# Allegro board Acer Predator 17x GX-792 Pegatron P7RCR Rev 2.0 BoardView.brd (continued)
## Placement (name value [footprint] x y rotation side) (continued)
C7024  0.22UF/16V  [VX_C0402_SMALL]  125.58 110.22 180 bottom
C7025  0.22UF/16V  [VX_C0402_SMALL]  125.58 109.33 180 bottom
C7026  0.1UF/6.3V  [VX_C0402_SMALL]  134.85 95.23 270 top
C7029  0.22UF/16V  [VX_C0402_SMALL]  127.74 110.47 180 bottom
C7030  0.22UF/16V  [VX_C0402_SMALL]  127.74 111.36 180 bottom
C7031  0.22UF/16V  [VX_C0402_SMALL]  124.82 112.63 180 bottom
C7032  0.22UF/16V  [VX_C0402_SMALL]  124.82 111.74 180 bottom
C7033  0.22UF/16V  [VX_C0402_SMALL]  127.74 113.01 180 bottom
C7034  0.22UF/16V  [VX_C0402_SMALL]  127.74 113.9 180 bottom
C7035  0.22UF/16V  [VX_C0402_SMALL]  125.08 114.28 180 bottom
C7036  0.22UF/16V  [VX_C0402_SMALL]  125.08 115.17 180 bottom
C7037  0.22UF/16V  [VX_C0402_SMALL]  127.74 116.44 180 bottom
C7038  0.22UF/16V  [VX_C0402_SMALL]  127.74 115.55 180 bottom
C7039  0.22UF/16V  [VX_C0402_SMALL]  124.82 116.95 180 bottom
C7040  0.22UF/16V  [VX_C0402_SMALL]  124.82 117.84 180 bottom
C7041  0.22UF/16V  [VX_C0402_SMALL]  127.74 118.22 180 bottom
C7042  0.22UF/16V  [VX_C0402_SMALL]  127.74 119.11 180 bottom
C7043  0.22UF/16V  [VX_C0402_SMALL]  124.82 119.49 180 bottom
C7044  0.22UF/16V  [VX_C0402_SMALL]  124.82 120.38 180 bottom
C7049  0.22UF/16V  [VX_C0402_SMALL]  127.74 120.89 180 bottom
C7050  0.22UF/16V  [VX_C0402_SMALL]  127.74 121.77 180 bottom
C7051  0.22UF/16V  [VX_C0402_SMALL]  125.46 122.16 180 bottom
C7052  0.22UF/16V  [VX_C0402_SMALL]  125.46 123.04 180 bottom
C7053  4.7uF/16V  [VX_C0603_SMALL]  135.87 91.17 180 top
C7054  22UF/6.3V  [VX_C0805_H55_SMALL]  123.42 125.46 270 bottom
C7055  22UF/6.3V  [VX_C0805_H55_SMALL]  132.44 82.4 180 top
C7100  0.1UF/6.3V  [VX_C0402_SMALL]  171.02 102 180 top
C7101  0.1UF/6.3V  [VX_C0402_SMALL]  149.21 57.51 180 top
C7102  22UF/6.3V  [VX_C0805_H55_SMALL]  149.21 58.91 180 top
C7103  0.1UF/6.3V  [VX_C0402_SMALL]  162.87 103.28 270 top
C7104  0.1UF/6.3V  [VX_C0402_SMALL]  171.04 95.05 180 top
C7105  0.1UF/6.3V  [VX_C0402_SMALL]  171.18 87.14 180 top
C7106  0.1UF/6.3V  [VX_C0402_SMALL]  167.75 84.52 90 top
C7107  0.1UF/6.3V  [VX_C0402_SMALL]  157.21 103.79 0 top
C7201  0.1UF/6.3V  [VX_C0402_SMALL]  152.15 92.75 0 top
C7202  0.1UF/6.3V  [VX_C0402_SMALL]  149.99 89.72 180 top
C7203  4.7uF/16V  [VX_C0603_SMALL]  134.85 88.52 180 top
C7204  1UF/6.3V  [VX_C0402_SMALL]  143.29 92.21 180 top
C7205  0.1UF/6.3V  [VX_C0402_SMALL]  152.13 90.28 0 top
C7206  10uF/25V  [VX_C0805_H57_SMALL_T02]  136.28 76.77 270 top
C7209  47uF/4V  [VX_C0805_H57_SMALL]  138.16 76.77 270 top
C7210  0.1UF/6.3V  [VX_C0402_SMALL]  150.43 81.66 270 top
C7211  22uF/4V  [VX_C0805_H55_SMALL]  138.8 81.03 270 top
C7212  0.1UF/6.3V  [VX_C0402_SMALL]  162.41 84.06 0 top
C7213  0.1UF/6.3V  [VX_C0402_SMALL]  168.69 103.36 270 top
C7214  0.1UF/6.3V  [VX_C0402_SMALL]  152.13 91.93 0 top
C7215  8.2PF/50V  [VX_C0402_SMALL]  139.55 73.15 270 bottom
C7216  10PF/50V  [VX_C0402_SMALL]  139.55 74.8 90 bottom
C7217  0.1UF/6.3V  [VX_C0402_SMALL]  149.6 83.05 270 top
C7219  4.7uF/16V  [VX_C0603_SMALL]  134.85 87.25 180 top
C7220  0.1UF/6.3V  [VX_C0402_SMALL]  152.13 86.8 0 top
C7221  0.1UF/6.3V  [VX_C0402_SMALL]  152.13 91.12 0 top
C7222  0.1UF/6.3V  [VX_C0402_SMALL]  149.94 87.64 0 top
C7223  0.1UF/6.3V  [VX_C0402_SMALL]  152.13 85.96 0 top
C7225  22UF/6.3V  [VX_C0805_H55_SMALL]  137.24 85.48 90 top
C7226  4.7uF/16V  [VX_C0603_SMALL]  139.71 86.11 180 top
C7230  0.1UF/6.3V  [VX_C0402_SMALL]  152.13 88.55 0 top
C7231  4.7uF/16V  [VX_C0603_SMALL]  134.85 85.98 180 top
C7234  0.1UF/6.3V  [VX_C0402_SMALL]  149.86 85.53 0 top
C7235  1UF/6.3V  [VX_C0402_SMALL]  152.13 87.64 0 top
C7301  1UF/6.3V  [VX_C0402_SMALL]  152.14 89.45 0 top
C7302  0.1UF/6.3V  [VX_C0402_SMALL]  143.29 91.32 180 top
C7400  0.1UF/6.3V  [VX_C0402_SMALL]  131.93 59.8 0 bottom
C7401  220PF/50V  [VX_C0402_SMALL]  152.41 62.57 0 bottom
C7402  220PF/50V  [VX_C0402_SMALL]  152.83 65.13 180 bottom
C7403  220PF/50V  [VX_C0402_SMALL]  148.01 64.75 270 bottom
C7404  220PF/50V  [VX_C0402_SMALL]  150.22 63.23 270 bottom
C7405  220PF/50V  [VX_C0402_SMALL]  134.98 56.5 180 bottom
C7406  220PF/50V  [VX_C0402_SMALL]  136.46 59.16 270 bottom
C7407  220PF/50V  [VX_C0402_SMALL]  136.46 54.08 270 bottom
C7408  220PF/50V  [VX_C0402_SMALL]  136.46 52.43 90 bottom
C7409  0.1UF/6.3V  [VX_C0402_SMALL]  147.73 53.83 90 bottom
C7410  0.1UF/6.3V  [VX_C0402_SMALL]  144.01 53.7 0 bottom
C7501  47uF/4V  [VX_C0805_H57_SMALL]  150.76 107.62 90 top
C7502  47uF/4V  [VX_C0805_H57_SMALL]  152.15 101.51 270 top
C7503  10uF/6.3V  [VX_C0603_H39_SMALL]  166.05 93.91 270 top
C7504  10uF/6.3V  [VX_C0603_H39_SMALL]  158.44 93.95 270 top
C7505  10uF/6.3V  [VX_C0603_H39_SMALL]  155.44 93.95 270 top
C7506  1UF/6.3V  [VX_C0402_SMALL]  171.12 101.18 180 top
C7507  1UF/6.3V  [VX_C0402_SMALL]  171.04 94.2 180 top
C7508  1UF/6.3V  [VX_C0402_SMALL]  171.13 95.9 180 top
C7509  1UF/6.3V  [VX_C0402_SMALL]  161.7 103.29 270 top
C7510  1UF/6.3V  [VX_C0402_SMALL]  160.04 103.29 270 top
C7511  1UF/6.3V  [VX_C0402_SMALL]  171.02 88.84 180 top
C7512  1UF/6.3V  [VX_C0402_SMALL]  171.18 86.3 180 top
C7513  1UF/6.3V  [VX_C0402_SMALL]  160.86 103.29 270 top
C7514  1UF/6.3V  [VX_C0402_SMALL]  164.08 103.79 0 top
C7515  1UF/6.3V  [VX_C0402_SMALL]  167.8 103.36 270 top
C7516  1UF/6.3V  [VX_C0402_SMALL]  164.45 84.51 90 top
C7517  1UF/6.3V  [VX_C0402_SMALL]  169.76 84 0 top
C7518  10uF/6.3V  [VX_C0603_H39_SMALL]  179.55 107.29 180 top
C7519  10uF/6.3V  [VX_C0603_H39_SMALL]  179.13 87.33 270 top
C7520  10uF/6.3V  [VX_C0603_H39_SMALL]  158.16 76.47 0 top
C7521  10uF/6.3V  [VX_C0603_H39_SMALL]  171.75 83.85 135 top
C7522  10uF/6.3V  [VX_C0603_H39_SMALL]  173.77 82.09 315 top
C7523  10uF/6.3V  [VX_C0603_H39_SMALL]  169.8 76.47 180 top
C7531  1UF/6.3V  [VX_C0402_SMALL]  169.53 96.7 0 top
C7532  1UF/6.3V  [VX_C0402_SMALL]  167.96 99.5 0 top
C7533  0.1UF/6.3V  [VX_C0402_SMALL]  157.85 84.41 90 top
C7534  1UF/6.3V  [VX_C0402_SMALL]  171.37 97.12 270 top
C7535  1UF/6.3V  [VX_C0402_SMALL]  164.8 99.5 180 top
C7536  1UF/6.3V  [VX_C0402_SMALL]  164.81 100.89 180 top
C7537  1UF/6.3V  [VX_C0402_SMALL]  158.49 100.99 0 top
C7538  1UF/6.3V  [VX_C0402_SMALL]  155.29 88.32 180 top
C7539  1UF/6.3V  [VX_C0402_SMALL]  167.96 98.1 0 top
C7540  1UF/6.3V  [VX_C0402_SMALL]  166.38 99.5 0 top
C7541  1UF/6.3V  [VX_C0402_SMALL]  160.07 100.99 180 top
C7542  1UF/6.3V  [VX_C0402_SMALL]  156.85 99.52 0 top
C7543  1UF/6.3V  [VX_C0402_SMALL]  163.21 99.5 180 top
C7544  1UF/6.3V  [VX_C0402_SMALL]  153.71 89.72 180 top
C7545  1UF/6.3V  [VX_C0402_SMALL]  153.71 88.32 180 top
C7546  1UF/6.3V  [VX_C0402_SMALL]  158.51 99.51 0 top
C7547  1UF/6.3V  [VX_C0402_SMALL]  156.86 89.72 0 top
C7548  1UF/6.3V  [VX_C0402_SMALL]  158.44 88.32 0 top
C7549  1UF/6.3V  [VX_C0402_SMALL]  156.86 88.32 0 top
C7550  1UF/6.3V  [VX_C0402_SMALL]  166.38 98.1 0 top
C7551  10uF/6.3V  [VX_C0603_H39_SMALL]  165.41 76.48 180 top
C7552  10uF/6.3V  [VX_C0603_H39_SMALL]  171.44 100 180 top
C7553  1UF/6.3V  [VX_C0402_SMALL]  158.74 84.41 90 top
C7554  1UF/6.3V  [VX_C0402_SMALL]  159.98 83.99 0 top
C7555  1UF/6.3V  [VX_C0402_SMALL]  161.2 84.51 90 top
C7556  1UF/6.3V  [VX_C0402_SMALL]  163.61 84.5 90 top
C7557  1UF/6.3V  [VX_C0402_SMALL]  165.65 84.05 0 top
C7558  1UF/6.3V  [VX_C0402_SMALL]  166.85 84.51 90 top
C7559  1UF/6.3V  [VX_C0402_SMALL]  168.56 84.5 90 top
C7560  10uF/6.3V  [VX_C0603_H39_SMALL]  179.55 103.17 180 top
C7561  10uF/6.3V  [VX_C0603_H39_SMALL]  179.55 101.43 180 top
C7562  10uF/6.3V  [VX_C0603_H39_SMALL]  171.77 103.94 225 top
C7563  10uF/6.3V  [VX_C0603_H39_SMALL]  171.4 91.99 180 top
C7564  1UF/6.3V  [VX_C0402_SMALL]  171.16 98.45 180 top
C7565  1UF/6.3V  [VX_C0402_SMALL]  171.02 87.99 180 top
C7566  1UF/6.3V  [VX_C0402_SMALL]  166.95 103.36 270 top
C7567  1UF/6.3V  [VX_C0402_SMALL]  165.67 103.79 180 top
C7568  1UF/6.3V  [VX_C0402_SMALL]  158.81 103.8 180 top
C7569  22uF/6.3V  [VX_C0603_H39_SMALL_T02]  182.56 80.32 270 top
C7570  22uF/6.3V  [VX_C0603_H39_SMALL_T02]  182.56 77.52 90 top
C7571  22uF/6.3V  [VX_C0603_H39_SMALL_T02]  149.81 115.82 270 top
C7572  22uF/6.3V  [VX_C0603_H39_SMALL_T02]  148.5 115.82 270 top
C7573  22uF/6.3V  [VX_C0603_H39_SMALL_T02]  179.01 91.75 90 top
C7574  22uF/6.3V  [VX_C0603_H39_SMALL_T02]  157.1 113.76 180 top
C7575  22uF/6.3V  [VX_C0603_H39_SMALL_T02]  160.72 113.72 0 top
C7576  22uF/6.3V  [VX_C0603_H39_SMALL_T02]  174.22 116.19 180 top
C7577  22uF/6.3V  [VX_C0603_H39_SMALL_T02]  165.92 115.81 0 top
C7578  22UF/6.3V  [VX_C0805_H55_SMALL]  145.78 107.09 270 top
C7579  22UF/6.3V  [VX_C0805_H55_SMALL]  147.87 105.46 270 top
C7580  22UF/6.3V  [VX_C0805_H55_SMALL]  150.02 103.37 270 top
C7581  22UF/6.3V  [VX_C0805_H55_SMALL]  143.77 107.1 270 top
C7582  10uF/6.3V  [VX_C0603_H39_SMALL]  158.74 97.43 270 top
C7583  10uF/6.3V  [VX_C0603_H39_SMALL]  164.66 93.95 90 top
C7584  10uF/6.3V  [VX_C0603_H39_SMALL]  167.59 93.94 90 top
C7585  10uF/6.3V  [VX_C0603_H39_SMALL]  156.94 93.95 270 top
C7586  1UF/6.3V  [VX_C0402_SMALL]  155.28 86.9 180 top
C7587  1UF/6.3V  [VX_C0402_SMALL]  165.67 102.95 0 top
C7588  1UF/6.3V  [VX_C0402_SMALL]  161.7 86.8 180 top
C7589  1UF/6.3V  [VX_C0402_SMALL]  166.4 88.27 180 top
C7590  10uF/6.3V  [VX_C0603_H39_SMALL]  163.17 93.95 270 top
C7591  1UF/6.3V  [VX_C0402_SMALL]  162.41 84.87 0 top
C7592  1UF/6.3V  [VX_C0402_SMALL]  165.65 84.9 0 top
C7593  1UF/6.3V  [VX_C0402_SMALL]  154.83 84.87 180 top
C7594  1UF/6.3V  [VX_C0402_SMALL]  169.53 99.5 0 top
C7595  1UF/6.3V  [VX_C0402_SMALL]  169.53 98.1 0 top
C7596  1UF/6.3V  [VX_C0402_SMALL]  158.46 86.9 0 top
C7597  1UF/6.3V  [VX_C0402_SMALL]  168.02 86.8 0 top
C7598  1UF/6.3V  [VX_C0402_SMALL]  153.71 91.09 180 top
C7599  1UF/6.3V  [VX_C0402_SMALL]  164.86 86.8 180 top
C7601  4.7uF/16V  [VX_C0603_SMALL]  142.67 142.25 180 top
C7602  4.7uF/16V  [VX_C0603_SMALL]  166.9 142.39 180 top
C7603  820PF/50V  [VX_C0402_SMALL]  159.37 134.42 180 top
C7604  820PF/50V  [VX_C0402_SMALL]  154.69 134.96 90 bottom
C7605  22uF/6.3V  [VX_C0603_H39_SMALL_T02]  172.57 139.6 90 top
C7606  22uF/6.3V  [VX_C0603_H39_SMALL_T02]  164.55 125.46 0 top
C7607  22uF/6.3V  [VX_C0603_H39_SMALL_T02]  172.88 131.81 90 top
C7608  22uF/6.3V  [VX_C0603_H39_SMALL_T02]  153.85 128.71 270 top
C7609  22uF/6.3V  [VX_C0603_H39_SMALL_T02]  171.17 142.27 0 top
C7610  10uF/6.3V  [VX_C0603_H39_SMALL]  163.94 142.34 0 top
C7611  10uF/6.3V  [VX_C0603_H39_SMALL]  159.44 140.43 270 bottom
C7612  10uF/6.3V  [VX_C0603_H39_SMALL]  161.26 125.21 180 top
C7613  10uF/6.3V  [VX_C0603_H39_SMALL]  171.14 125.33 0 top
C7614  10uF/6.3V  [VX_C0603_H39_SMALL]  159.57 128.89 270 top
C7615  10uF/6.3V  [VX_C0603_H39_SMALL]  159.45 139.43 90 top
C7616  1UF/6.3V  [VX_C0402_SMALL]  164.93 129.52 270 top
C7617  1UF/6.3V  [VX_C0402_SMALL]  172.36 135.66 270 bottom
C7618  1UF/6.3V  [VX_C0402_SMALL]  140.53 138.56 270 bottom
C7619  1UF/6.3V  [VX_C0402_SMALL]  172.37 135.69 270 top
C7620  1UF/6.3V  [VX_C0402_SMALL]  172.36 137.39 90 bottom
C7621  1UF/6.3V  [VX_C0402_SMALL]  159.72 128.88 270 bottom
C7622  1UF/6.3V  [VX_C0402_SMALL]  159.68 126.61 270 top
C7623  1UF/6.3V  [VX_C0402_SMALL]  167.53 132.24 90 top
C7624  1UF/6.3V  [VX_C0402_SMALL]  159.72 130.57 90 bottom
C7625  1UF/6.3V  [VX_C0402_SMALL]  172.4 137.34 90 top
C7626  1UF/6.3V  [VX_C0402_SMALL]  153.47 131.29 90 bottom
C7627  1UF/6.3V  [VX_C0402_SMALL]  165.56 136 90 top
C7628  1UF/6.3V  [VX_C0402_SMALL]  151.31 142.37 180 bottom
C7629  1UF/6.3V  [VX_C0402_SMALL]  167.7 134.73 0 top
C7630  1UF/6.3V  [VX_C0402_SMALL]  164.95 131.53 90 top
C7631  1UF/6.3V  [VX_C0402_SMALL]  166.83 128.91 90 top
C7632  1UF/6.3V  [VX_C0402_SMALL]  165.59 137.98 270 top
C7633  1UF/6.3V  [VX_C0402_SMALL]  168.48 137.65 0 top
C7634  1UF/6.3V  [VX_C0402_SMALL]  168.93 142.31 0 top
C7635  1UF/6.3V  [VX_C0402_SMALL]  168.71 125.36 180 top
C7636  10uF/6.3V  [VX_C0603_H39_SMALL]  140.61 131.84 270 top
C7637  10uF/6.3V  [VX_C0603_H39_SMALL]  140.68 138.14 270 top
C7638  10uF/6.3V  [VX_C0603_H39_SMALL]  161.25 142.37 0 top
C7639  10uF/6.3V  [VX_C0603_H39_SMALL]  153.53 136.78 270 top
C7640  10uF/6.3V  [VX_C0603_H39_SMALL]  140.43 140.68 270 bottom
C7641  1UF/6.3V  [VX_C0402_SMALL]  140.74 140.55 270 top
C7642  1UF/6.3V  [VX_C0402_SMALL]  146.69 136.05 90 top
C7643  1UF/6.3V  [VX_C0402_SMALL]  147.55 136.68 90 top
C7644  1UF/6.3V  [VX_C0402_SMALL]  147.55 138.6 90 top
C7645  1UF/6.3V  [VX_C0402_SMALL]  148.19 128.86 90 top
C7646  1UF/6.3V  [VX_C0402_SMALL]  148.16 131.5 90 top
C7647  1UF/6.3V  [VX_C0402_SMALL]  146.28 139.99 90 top
C7648  1UF/6.3V  [VX_C0402_SMALL]  146.23 129.47 90 top
C7649  1UF/6.3V  [VX_C0402_SMALL]  153.45 140.67 270 top
C7650  1UF/6.3V  [VX_C0402_SMALL]  153.52 138.84 270 top
C7651  1UF/6.3V  [VX_C0402_SMALL]  159.72 136.63 270 bottom
C7652  1UF/6.3V  [VX_C0402_SMALL]  159.72 138.25 270 bottom
C7653  1UF/6.3V  [VX_C0402_SMALL]  153.35 129.68 90 bottom
C7654  22uF/6.3V  [VX_C0603_H39_SMALL_T02]  147.65 142.25 0 top
C7655  1UF/6.3V  [VX_C0402_SMALL]  146.19 132.04 90 top
C7656  1UF/6.3V  [VX_C0402_SMALL]  140.8 129.27 270 top
C7657  1UF/6.3V  [VX_C0402_SMALL]  153.21 136.93 270 bottom
C7658  1UF/6.3V  [VX_C0402_SMALL]  140.55 136.81 90 bottom
C7659  1UF/6.3V  [VX_C0402_SMALL]  153.35 127.99 90 bottom
C7660  22uF/6.3V  [VX_C0603_H39_SMALL_T02]  153.42 139.68 90 bottom
C7661  1UF/6.3V  [VX_C0402_SMALL]  144.72 142.14 0 top
C7662  1UF/6.3V  [VX_C0402_SMALL]  144.43 126.38 0 top
C7663  22uF/6.3V  [VX_C0603_H39_SMALL_T02]  148.19 142.33 0 bottom
C7664  22uF/6.3V  [VX_C0603_H39_SMALL_T02]  152.04 125.93 0 top
C7665  22uF/6.3V  [VX_C0603_H39_SMALL_T02]  172.83 127.39 270 top
C7666  10uF/6.3V  [VX_C0603_H39_SMALL]  149.21 125.88 180 top
C7701  4.7uF/16V  [VX_C0603_SMALL]  177.23 142.26 180 top
C7702  4.7uF/16V  [VX_C0603_SMALL]  210.6 115.15 90 top
C7703  820PF/50V  [VX_C0402_SMALL]  188.4 134.3 270 bottom
C7704  820PF/50V  [VX_C0402_SMALL]  202.9 122.76 90 top
C7705  10uF/6.3V  [VX_C0603_H39_SMALL]  208.55 122.33 180 bottom
C7706  10uF/6.3V  [VX_C0603_H39_SMALL]  210.47 120.51 270 top
C7707  10uF/6.3V  [VX_C0603_H39_SMALL]  195.73 109.16 180 top
C7708  10uF/6.3V  [VX_C0603_H39_SMALL]  175.31 138.44 270 top
C7709  10uF/6.3V  [VX_C0603_H39_SMALL]  177.29 125.33 180 top
C7710  10uF/6.3V  [VX_C0603_H39_SMALL]  188.04 140.11 90 bottom
C7711  10uF/6.3V  [VX_C0603_H39_SMALL]  185.86 142.37 0 top
C7712  10uF/6.3V  [VX_C0603_H39_SMALL]  175.14 127.18 270 top
C7713  1UF/6.3V  [VX_C0402_SMALL]  180.91 132.11 90 top
C7714  1UF/6.3V  [VX_C0402_SMALL]  188.04 136.28 270 bottom
C7715  1UF/6.3V  [VX_C0402_SMALL]  182.25 138.64 90 top
C7716  1UF/6.3V  [VX_C0402_SMALL]  181.06 135.49 90 top
C7717  1UF/6.3V  [VX_C0402_SMALL]  179.69 136.71 270 top
C7718  1UF/6.3V  [VX_C0402_SMALL]  182.23 136.68 90 top
C7719  1UF/6.3V  [VX_C0402_SMALL]  180.88 129.5 90 top
C7720  1UF/6.3V  [VX_C0402_SMALL]  182.86 129.5 270 top
C7721  1UF/6.3V  [VX_C0402_SMALL]  182.84 131.55 90 top
C7722  10uF/6.3V  [VX_C0603_H39_SMALL]  193.38 118.91 270 top
C7723  10uF/6.3V  [VX_C0603_H39_SMALL]  210.42 117.83 270 top
C7724  1UF/6.3V  [VX_C0402_SMALL]  175.49 129.29 270 top
C7725  1UF/6.3V  [VX_C0402_SMALL]  188.25 127.85 90 bottom
C7726  1UF/6.3V  [VX_C0402_SMALL]  175.39 136.07 270 top
C7727  1UF/6.3V  [VX_C0402_SMALL]  175.44 140.61 270 top
C7728  22uF/6.3V  [VX_C0603_H39_SMALL_T02]  187.93 136.91 270 top
C7729  1UF/6.3V  [VX_C0402_SMALL]  185.05 142.22 180 bottom
C7730  1UF/6.3V  [VX_C0402_SMALL]  175.27 136.16 270 bottom
C7731  1UF/6.3V  [VX_C0402_SMALL]  188.22 129.49 270 bottom
C7732  1UF/6.3V  [VX_C0402_SMALL]  188.04 137.9 90 bottom
C7733  1UF/6.3V  [VX_C0402_SMALL]  172.7 129.6 90 top
C7734  22uF/6.3V  [VX_C0603_H39_SMALL_T02]  187.93 139.85 90 top
C7735  1UF/6.3V  [VX_C0402_SMALL]  179.32 142.18 0 top
C7736  1UF/6.3V  [VX_C0402_SMALL]  179.68 125.72 0 top
C7737  22uF/6.3V  [VX_C0603_H39_SMALL_T02]  175.22 140.25 270 bottom
C7738  22uF/6.3V  [VX_C0603_H39_SMALL_T02]  175.19 131.61 270 top
C7739  22uF/6.3V  [VX_C0603_H39_SMALL_T02]  188.55 129.08 270 top
C7740  10uF/6.3V  [VX_C0603_H39_SMALL]  182.62 142.22 0 top
C7741  1UF/6.3V  [VX_C0402_SMALL]  195.54 122.71 180 top
C7742  1UF/6.3V  [VX_C0402_SMALL]  206.53 116.72 0 top
C7743  1UF/6.3V  [VX_C0402_SMALL]  205.57 113.72 270 top
C7744  1UF/6.3V  [VX_C0402_SMALL]  203.97 116.67 0 top
C7745  1UF/6.3V  [VX_C0402_SMALL]  205.31 115.48 0 top
C7746  1UF/6.3V  [VX_C0402_SMALL]  199.48 117.28 0 top
C7747  1UF/6.3V  [VX_C0402_SMALL]  200.67 114.69 180 top
C7748  1UF/6.3V  [VX_C0402_SMALL]  196.83 117.3 0 top
C7749  1UF/6.3V  [VX_C0402_SMALL]  205.57 109.51 0 bottom
C7750  1UF/6.3V  [VX_C0402_SMALL]  193.4 121.04 90 top
C7751  1UF/6.3V  [VX_C0402_SMALL]  196.26 122.71 0 bottom
C7752  1UF/6.3V  [VX_C0402_SMALL]  197.85 109.2 180 top
C7753  1UF/6.3V  [VX_C0402_SMALL]  205.57 109.58 0 top
C7754  22uF/6.3V  [VX_C0603_H39_SMALL_T02]  200.04 109.18 0 top
C7755  1UF/6.3V  [VX_C0402_SMALL]  203.84 109.53 180 top
C7756  1UF/6.3V  [VX_C0402_SMALL]  198.41 122.77 0 bottom
C7757  1UF/6.3V  [VX_C0402_SMALL]  203.84 109.56 180 bottom
C7758  1UF/6.3V  [VX_C0402_SMALL]  197.29 122.71 180 top
C7759  1UF/6.3V  [VX_C0402_SMALL]  196.83 115.25 0 top
C7760  22uF/6.3V  [VX_C0603_H39_SMALL_T02]  210.5 119.61 90 bottom
C7761  1UF/6.3V  [VX_C0402_SMALL]  193.62 113.73 90 top
C7762  1UF/6.3V  [VX_C0402_SMALL]  210.32 113.11 270 top
C7763  22uF/6.3V  [VX_C0603_H39_SMALL_T02]  205.66 122.48 180 top
C7764  22uF/6.3V  [VX_C0603_H39_SMALL_T02]  205.76 122.36 180 bottom
C7765  22uF/6.3V  [VX_C0603_H39_SMALL_T02]  193.63 110.79 270 top
C7766  10uF/6.3V  [VX_C0603_H39_SMALL]  207.84 109.39 0 bottom
C7801  4.7uF/16V  [VX_C0603_SMALL]  209.9 105.06 90 top
C7802  4.7uF/16V  [VX_C0603_SMALL]  210.42 76.28 270 top
C7803  820PF/50V  [VX_C0402_SMALL]  203.09 93.03 0 bottom
C7804  820PF/50V  [VX_C0402_SMALL]  202.31 87.68 0 top
C7805  10uF/6.3V  [VX_C0603_H39_SMALL]  205.19 93.47 0 top
C7806  10uF/6.3V  [VX_C0603_H39_SMALL]  195.45 74.1 0 top
C7807  10uF/6.3V  [VX_C0603_H39_SMALL]  210.25 85.49 270 top
C7808  10uF/6.3V  [VX_C0603_H39_SMALL]  195.55 93.17 0 top
C7809  10uF/6.3V  [VX_C0603_H39_SMALL]  210.08 95.47 90 top
C7810  10uF/6.3V  [VX_C0603_H39_SMALL]  207.16 106.51 180 top
C7811  10uF/6.3V  [VX_C0603_H39_SMALL]  208.31 87.35 180 bottom
C7812  10uF/6.3V  [VX_C0603_H39_SMALL]  204.82 106.48 0 bottom
C7813  1UF/6.3V  [VX_C0402_SMALL]  198.53 98.74 180 top
C7814  1UF/6.3V  [VX_C0402_SMALL]  205.05 100.64 0 top
C7815  1UF/6.3V  [VX_C0402_SMALL]  209.91 95.78 90 bottom
C7816  1UF/6.3V  [VX_C0402_SMALL]  196.45 100.72 180 top
C7817  1UF/6.3V  [VX_C0402_SMALL]  204.28 99.61 0 top
C7818  1UF/6.3V  [VX_C0402_SMALL]  199.07 100.69 180 top
C7819  1UF/6.3V  [VX_C0402_SMALL]  202.75 103 270 top
C7820  1UF/6.3V  [VX_C0402_SMALL]  206.32 99.35 0 top
C7821  1UF/6.3V  [VX_C0402_SMALL]  197.47 93.4 0 bottom
C7822  10uF/6.3V  [VX_C0603_H39_SMALL]  207.62 74.3 0 top
C7823  10uF/6.3V  [VX_C0603_H39_SMALL]  205.5 87.38 180 bottom
C7824  1UF/6.3V  [VX_C0402_SMALL]  195.43 106.48 180 top
C7825  1UF/6.3V  [VX_C0402_SMALL]  196.98 87.89 180 top
C7826  1UF/6.3V  [VX_C0402_SMALL]  199.22 106.51 180 top
C7827  1UF/6.3V  [VX_C0402_SMALL]  196.58 98.74 0 top
C7828  22uF/6.3V  [VX_C0603_H39_SMALL_T02]  194.76 88.02 180 top
C7829  1UF/6.3V  [VX_C0402_SMALL]  204.73 93.66 180 bottom
C7830  1UF/6.3V  [VX_C0402_SMALL]  197.36 106.46 180 top
C7831  1UF/6.3V  [VX_C0402_SMALL]  197.72 93.2 0 top
C7832  1UF/6.3V  [VX_C0402_SMALL]  196.53 87.84 180 bottom
C7833  1UF/6.3V  [VX_C0402_SMALL]  199.12 93.4 0 bottom
C7834  1UF/6.3V  [VX_C0402_SMALL]  209.56 102.65 270 top
C7835  22uF/6.3V  [VX_C0603_H39_SMALL_T02]  193.39 96.45 90 top
C7836  22uF/6.3V  [VX_C0603_H39_SMALL_T02]  207.98 93.5 180 top
C7837  1UF/6.3V  [VX_C0402_SMALL]  193.45 103.33 270 top
C7838  22uF/6.3V  [VX_C0603_H39_SMALL_T02]  207.05 93.63 180 bottom
C7839  22uF/6.3V  [VX_C0603_H39_SMALL_T02]  205.47 87.39 180 top
C7840  10uF/6.3V  [VX_C0603_H39_SMALL]  210.08 98.21 270 top
C7841  1UF/6.3V  [VX_C0402_SMALL]  203.61 74.45 180 bottom
C7842  1UF/6.3V  [VX_C0402_SMALL]  205.67 81.62 180 top
C7843  1UF/6.3V  [VX_C0402_SMALL]  207.68 80.35 0 top
C7844  1UF/6.3V  [VX_C0402_SMALL]  203.63 81.55 0 top
C7845  1UF/6.3V  [VX_C0402_SMALL]  196.58 82.23 0 top
C7846  1UF/6.3V  [VX_C0402_SMALL]  204.93 80.37 0 top
C7847  1UF/6.3V  [VX_C0402_SMALL]  200.41 79.66 180 top
C7848  1UF/6.3V  [VX_C0402_SMALL]  203.62 74.47 180 top
C7849  1UF/6.3V  [VX_C0402_SMALL]  197.49 74.15 180 top
C7850  1UF/6.3V  [VX_C0402_SMALL]  199.16 82.15 0 top
C7851  1UF/6.3V  [VX_C0402_SMALL]  205.37 74.46 0 bottom
C7852  1UF/6.3V  [VX_C0402_SMALL]  193.3 76.72 270 top
C7853  1UF/6.3V  [VX_C0402_SMALL]  207.73 87.31 180 top
C7854  22uF/6.3V  [VX_C0603_H39_SMALL_T02]  199.71 74.05 180 top
C7855  1UF/6.3V  [VX_C0402_SMALL]  209.91 79.76 90 bottom
C7856  1UF/6.3V  [VX_C0402_SMALL]  198.23 87.81 0 bottom
C7857  1UF/6.3V  [VX_C0402_SMALL]  207.87 122.35 180 top
C7858  1UF/6.3V  [VX_C0402_SMALL]  205.34 74.47 0 top
C7859  1UF/6.3V  [VX_C0402_SMALL]  196.58 80.25 0 top
C7860  22uF/6.3V  [VX_C0603_H39_SMALL_T02]  207.71 106.41 180 bottom
C7861  1UF/6.3V  [VX_C0402_SMALL]  210.29 79.43 90 top
C7862  1UF/6.3V  [VX_C0402_SMALL]  193.24 79.32 90 top
C7863  22uF/6.3V  [VX_C0603_H39_SMALL_T02]  207.63 74.37 0 bottom
C7864  22uF/6.3V  [VX_C0603_H39_SMALL_T02]  204.34 106.59 0 top
C7865  22uF/6.3V  [VX_C0603_H39_SMALL_T02]  193.15 84.01 90 top
C7866  10uF/6.3V  [VX_C0603_H39_SMALL]  210.31 82.79 270 top
C7901  4.7uF/16V  [VX_C0603_SMALL]  182.4 44.1 180 top
C7902  4.7uF/16V  [VX_C0603_SMALL]  160.86 45.49 0 top
C7903  820PF/50V  [VX_C0402_SMALL]  173.67 53.25 90 bottom
C7904  820PF/50V  [VX_C0402_SMALL]  168.05 53.05 0 top
C7905  10uF/6.3V  [VX_C0603_H39_SMALL]  154.84 56.11 270 top
C7906  10uF/6.3V  [VX_C0603_H39_SMALL]  154.9 60.21 90 top
C7907  10uF/6.3V  [VX_C0603_H39_SMALL]  168.26 60.93 90 top
C7908  10uF/6.3V  [VX_C0603_H39_SMALL]  166.32 45.5 180 top
C7909  10uF/6.3V  [VX_C0603_H39_SMALL]  178.34 62.58 0 top
C7910  10uF/6.3V  [VX_C0603_H39_SMALL]  174.44 48.07 270 bottom
C7911  10uF/6.3V  [VX_C0603_H39_SMALL]  175.42 62.55 180 top
C7912  10uF/6.3V  [VX_C0603_H39_SMALL]  167.94 47.34 90 bottom
C7913  1UF/6.3V  [VX_C0402_SMALL]  180.19 51.14 270 top
C7914  1UF/6.3V  [VX_C0402_SMALL]  187 51.77 90 top
C7915  1UF/6.3V  [VX_C0402_SMALL]  186.95 58.58 90 top
C7916  1UF/6.3V  [VX_C0402_SMALL]  181.57 55.73 270 top
C7917  1UF/6.3V  [VX_C0402_SMALL]  183.8 52.81 180 top
C7918  1UF/6.3V  [VX_C0402_SMALL]  179.53 56.34 270 top
C7919  1UF/6.3V  [VX_C0402_SMALL]  180.17 49.18 270 top
C7920  1UF/6.3V  [VX_C0402_SMALL]  181.59 58.35 270 top
C7921  1UF/6.3V  [VX_C0402_SMALL]  179.51 58.27 90 top
C7922  10uF/6.3V  [VX_C0603_H39_SMALL]  167.89 50.21 90 bottom
C7923  10uF/6.3V  [VX_C0603_H39_SMALL]  166.2 62.35 0 top
C7924  1UF/6.3V  [VX_C0402_SMALL]  174.2 57.44 270 bottom
C7925  1UF/6.3V  [VX_C0402_SMALL]  174.2 59.7 270 bottom
C7926  1UF/6.3V  [VX_C0402_SMALL]  176.87 45.68 0 bottom
C7927  1UF/6.3V  [VX_C0402_SMALL]  168.08 58.81 90 top
C7928  22uF/6.3V  [VX_C0603_H39_SMALL_T02]  173.88 59.33 90 top
C7929  1UF/6.3V  [VX_C0402_SMALL]  181.33 51.5 90 top
C7930  1UF/6.3V  [VX_C0402_SMALL]  167.94 47.67 90 top
C7931  1UF/6.3V  [VX_C0402_SMALL]  186.98 50.12 90 top
C7932  1UF/6.3V  [VX_C0402_SMALL]  187.13 46.74 270 bottom
C7933  1UF/6.3V  [VX_C0402_SMALL]  162.13 51.87 270 top
C7934  1UF/6.3V  [VX_C0402_SMALL]  186.97 60.41 270 top
C7935  22uF/6.3V  [VX_C0603_H39_SMALL_T02]  156.55 62.51 180 top
C7936  22uF/6.3V  [VX_C0603_H39_SMALL_T02]  168.04 50.18 90 top
C7937  1UF/6.3V  [VX_C0402_SMALL]  182.63 45.35 180 top
C7938  22uF/6.3V  [VX_C0603_H39_SMALL_T02]  187.31 47.87 270 top
C7939  22uF/6.3V  [VX_C0603_H39_SMALL_T02]  187.38 56.3 90 top
C7940  10uF/6.3V  [VX_C0603_H39_SMALL]  174.3 50.98 90 bottom
C7941  1UF/6.3V  [VX_C0402_SMALL]  168.03 57.33 270 bottom
C7942  1UF/6.3V  [VX_C0402_SMALL]  160.75 49.89 270 top
C7943  1UF/6.3V  [VX_C0402_SMALL]  155.33 52.15 90 top
C7944  1UF/6.3V  [VX_C0402_SMALL]  162.69 58.33 90 top
C7945  1UF/6.3V  [VX_C0402_SMALL]  155.28 50.43 270 top
C7946  1UF/6.3V  [VX_C0402_SMALL]  162.11 49.18 270 top
C7947  1UF/6.3V  [VX_C0402_SMALL]  187.26 50.88 270 bottom
C7948  1UF/6.3V  [VX_C0402_SMALL]  187.26 49.21 90 bottom
C7949  1UF/6.3V  [VX_C0402_SMALL]  175.19 138.06 270 bottom
C7950  1UF/6.3V  [VX_C0402_SMALL]  168.03 58.94 90 bottom
C7951  1UF/6.3V  [VX_C0402_SMALL]  155.23 50.45 270 bottom
C7952  1UF/6.3V  [VX_C0402_SMALL]  162.73 56.37 270 top
C7953  1UF/6.3V  [VX_C0402_SMALL]  155.35 52.15 90 bottom
C7954  22uF/6.3V  [VX_C0603_H39_SMALL_T02]  179.37 45.65 180 top
C7955  1UF/6.3V  [VX_C0402_SMALL]  155.15 48.17 270 bottom
C7956  1UF/6.3V  [VX_C0402_SMALL]  160.1 55.02 90 top
C7957  1UF/6.3V  [VX_C0402_SMALL]  160 52.94 180 top
C7958  1UF/6.3V  [VX_C0402_SMALL]  154.95 58.17 270 top
C7959  1UF/6.3V  [VX_C0402_SMALL]  160.74 58.94 270 top
C7960  22uF/6.3V  [VX_C0603_H39_SMALL_T02]  156.38 45.3 180 top
C7961  1UF/6.3V  [VX_C0402_SMALL]  158.93 62.21 0 top
C7962  1UF/6.3V  [VX_C0402_SMALL]  158.79 45.46 180 top
C7963  22uF/6.3V  [VX_C0603_H39_SMALL_T02]  163.3 62.41 180 top
C7964  22uF/6.3V  [VX_C0603_H39_SMALL_T02]  174.22 51 90 top
C7965  22uF/6.3V  [VX_C0603_H39_SMALL_T02]  155.17 48.16 270 top
C7966  10uF/6.3V  [VX_C0603_H39_SMALL]  176.22 45.42 180 top
C8000  330PF/50V  [VX_C0402_SMALL]  57.13 185.32 0 top
C8001  0.22UF/16V  [VX_C0402_SMALL]  50.91 182.05 0 top
C8002  330PF/50V  [VX_C0402_SMALL]  53.04 184.56 180 top
C8003  330PF/50V  [VX_C0402_SMALL]  50.91 181.16 0 top
C8004  330PF/50V  [VX_C0402_SMALL]  50.61 181.49 270 bottom
C8005  10PF/50V  [VX_C0402_SMALL]  48.49 182.78 180 bottom
C8006  330PF/50V  [VX_C0402_SMALL]  48.49 182.05 0 top
C8007  1200PF/50V  [VX_C0402_SMALL]  48.49 185.42 180 top
C8008  220PF/50V  [VX_C0402_SMALL]  48.49 186.34 180 top
C8009  390PF/50V  [VX_C0402_SMALL]  62.69 186.47 180 bottom
C8010  4700PF/50V  [VX_C0402_SMALL]  58.65 191.16 270 bottom
C8011  0.022UF/25V  [VX_C0402_SMALL]  52.43 177.96 90 bottom
C8012  6800PF/25V  [VX_C0402_SMALL]  48.49 181.89 180 bottom
C8013  330PF/50V  [VX_C0402_SMALL]  66.78 183.29 90 bottom
C8014  330PF/50V  [VX_C0402_SMALL]  61.32 191.16 270 bottom
C8015  18PF/50V  [VX_C0402_SMALL]  61.72 187.41 180 bottom
C8016  8200PF/16V  [VX_C0402_SMALL]  62.21 191.16 270 bottom
C8017  0.022UF/25V  [VX_C0402_SMALL]  54.84 177.96 90 bottom
C8018  2200PF/50V  [VX_C0402_SMALL]  56.62 177.75 270 bottom
C8019  0.022UF/25V  [VX_C0402_SMALL]  53.32 177.96 90 bottom
C8020  0.1UF/25V  [VX_C0402_SMALL]  47.48 177.45 270 bottom
C8021  1000PF/50V  [VX_C0402_SMALL]  63.89 185.12 90 bottom
C8022  330PF/50V  [VX_C0402_SMALL]  63.1 182.91 180 bottom
C8023  0.22UF/16V  [VX_C0402_SMALL]  64.69 182.91 180 bottom
C8024  3300PF/50V  [VX_C0402_SMALL]  56.06 181.77 90 top
C8025  0.22UF/16V  [VX_C0402_SMALL]  54.84 183.67 180 top
C8026  0.068UF/16V  [VX_C0402_SMALL]  49.64 177.45 90 bottom
C8027  0.027UF/25V  [VX_C0402_SMALL]  67.04 181.51 270 bottom
C8028  0.1UF/25V  [VX_C0402_SMALL]  66.15 181.51 90 bottom
C8029  0.022UF/25V  [VX_C0402_SMALL]  67.5 180.24 0 bottom
C8030  0.022UF/25V  [VX_C0402_SMALL]  64.75 181 0 bottom
C8031  8200PF/16V  [VX_C0402_SMALL]  62.68 176.2 180 bottom
C8032  33PF/50V  [VX_C0402_SMALL]  61.83 178.34 180 bottom
C8033  470PF/50V  [VX_C0402_SMALL]  58.2 184.38 0 top
C8034  2200PF/50V  [VX_C0402_SMALL]  71.61 181.89 0 bottom
C8035  330PF/50V  [VX_C0402_SMALL]  61.07 179.73 270 bottom
C8036  0.15uF/10V  [VX_C0402_SMALL]  69.3 181.64 0 bottom
C8053  1000PF/50V  [VX_C0402_SMALL]  70.59 151.62 0 bottom
C8054  0.22UF/16V  [VX_C0402_SMALL]  66.91 148.19 0 bottom
C8055  0.22UF/16V  [VX_C0402_SMALL]  79.48 181.97 270 bottom
C8059  1000PF/50V  [VX_C0402_SMALL]  82.91 178.29 270 bottom
C8060  0.22UF/16V  [VX_C0402_SMALL]  67.16 166.73 0 bottom
C8064  1000PF/50V  [VX_C0402_SMALL]  70.85 170.16 0 bottom
C8065  1UF/16V  [VX_C0402_SMALL]  66.91 147.17 0 bottom
C8066  1UF/16V  [VX_C0402_SMALL]  78.16 182.46 180 bottom
C8067  1UF/16V  [VX_C0402_SMALL]  67.16 165.72 0 bottom
C8068  1UF/25V  [VX_C0402_H24_SMALL]  70.47 144.25 180 bottom
C8069  1UF/25V  [VX_C0402_H24_SMALL]  75.55 178.42 90 bottom
C8070  1UF/25V  [VX_C0402_H24_SMALL]  70.72 162.8 180 bottom
C8071  1500PF/50V  [VX_C0603_SMALL]  74.5 154.82 0 bottom
C8072  1500PF/50V  [VX_C0603_SMALL]  86.59 174.1 180 bottom
C8073  1500PF/50V  [VX_C0603_SMALL]  74.78 170.29 0 bottom
C8074  22UF/6.3V  [VX_C0603_H39_SMALL]  84.44 145.27 0 bottom
C8075  22UF/6.3V  [VX_C0603_H39_SMALL]  84.44 144 0 bottom
C8076  22UF/6.3V  [VX_C0603_H39_SMALL]  90.66 144 180 bottom
C8077  22UF/6.3V  [VX_C0603_H39_SMALL]  90.66 145.27 180 bottom
C8078  22UF/6.3V  [VX_C0603_H39_SMALL]  105.55 117.13 180 top
C8079  22UF/6.3V  [VX_C0603_H39_SMALL]  97.88 120.89 0 top
C8080  22UF/6.3V  [VX_C0603_H39_SMALL]  100.5 120.94 180 top
C8081  22UF/6.3V  [VX_C0603_H39_SMALL]  105.55 119.67 180 top
C8082  22UF/6.3V  [VX_C0603_H39_SMALL]  100.5 119.67 180 top
C8083  22UF/6.3V  [VX_C0603_H39_SMALL]  102.76 120.94 0 top
C8084  22UF/6.3V  [VX_C0603_H39_SMALL]  105.55 120.94 180 top
C8085  22UF/6.3V  [VX_C0603_H39_SMALL]  102.76 119.67 0 top
C8086  0.22UF/16V  [VX_C0402_SMALL]  99.04 156.95 90 top
C8087  10UF/25V  [VX_C0805_H57_SMALL]  90.91 164.25 180 top
C8088  10UF/25V  [VX_C0805_H57_SMALL]  90.91 162.52 180 top
C8089  10UF/25V  [VX_C0805_H57_SMALL]  90.91 160.8 180 top
C8090  1000PF/50V  [VX_C0402_SMALL]  90.33 165.57 180 top
C8091  22UF/6.3V  [VX_C0603_H39_SMALL]  84.44 144 0 top
C8092  22UF/6.3V  [VX_C0603_H39_SMALL]  90.66 145.9 180 top
C8093  22UF/6.3V  [VX_C0603_H39_SMALL]  99.07 139.05 180 top
C8094  22UF/6.3V  [VX_C0603_H39_SMALL]  104.93 137.45 270 top
C8095  22UF/6.3V  [VX_C0603_H39_SMALL]  96.91 141.54 180 top
C8096  22UF/6.3V  [VX_C0603_H39_SMALL]  97.88 119.62 0 top
C8097  22UF/6.3V  [VX_C0603_H39_SMALL]  97.88 118.35 0 top
C8098  22UF/6.3V  [VX_C0603_H39_SMALL]  97.87 140.29 180 top
C8099  22UF/6.3V  [VX_C0603_H39_SMALL]  100.5 117.13 180 top
C8100  0.1UF/10V  [VX_C0402_SMALL]  263.95 60.06 90 top
C8101  1UF/25V  [VX_C0603_SMALL]  265.18 58.12 0 top
C8102  10UF/25V  [VX_C0805_H57_SMALL]  275.7 20.68 270 bottom
C8103  0.1UF/25V  [VX_C0402_SMALL]  273.89 20.43 270 bottom
C8104  10UF/25V  [VX_C0805_H57_SMALL]  267.06 64.37 180 bottom
C8105  10UF/25V  [VX_C0805_H57_SMALL]  267.06 62.59 180 bottom
C8106  0.1UF/25V  [VX_C0402_SMALL]  266.9 65.64 180 bottom
C8107  0.1UF/25V  [VX_C0603_SMALL]  260.08 63.74 270 top
C8108  0.1UF/25V  [VX_C0603_SMALL]  260.58 55.61 270 top
C8109  0.1UF/10V  [VX_C0402_SMALL]  285.98 79.48 90 bottom
C8110  0.1UF/10V  [VX_C0402_SMALL]  256.77 27.79 0 top
C8111  1500PF/50V  [VX_C0402_SMALL]  265.66 67.32 270 bottom
C8112  1500PF/50V  [VX_C0402_SMALL]  273.01 20.43 270 bottom
C8113  39PF/50V  [VX_C0402_SMALL]  258.04 60.69 270 top
C8114  39PF/50V  [VX_C0402_SMALL]  257.89 56.34 180 top
C8115  0.1UF/10V  [VX_C0402_SMALL]  256.77 61.96 180 top
C8116  0.1UF/10V  [VX_C0402_SMALL]  257.89 54.67 180 top
C8117  0.1UF/10V  [VX_C0402_SMALL]  257.66 59.42 180 top
C8118  0.1UF/25V  [VX_C0402_SMALL]  263.25 65.64 180 top
C8119  0.1UF/25V  [VX_C0603_SMALL]  261.98 74.74 270 top
C8120  0.1UF/25V  [VX_C0603_SMALL]  258.81 70.09 180 top
C8121  0.1UF/25V  [VX_C0603_SMALL]  257.41 74.02 270 top
C8122  0.1UF/25V  [VX_C0603_SMALL]  256.52 70.09 180 top
C8123  0.1UF/25V  [VX_C0603_SMALL]  255 75.93 0 top
C8132  10UF/25V  [VX_C0805_H57_SMALL]  276.59 18.35 180 bottom
C8202  1500PF/50V  [VX_C0402_SMALL]  228.2 13.7 0 top
C8203  10UF/25V  [VX_C0805_H57_SMALL]  227.9 11.51 0 top
C8205  0.1UF/25V  [VX_C0603_SMALL]  193.27 16.87 0 top
C8206  1UF/16V  [VX_C0402_SMALL]  225.79 17.51 0 top
C8207  0.22UF/25V  [VX_C0603_SMALL]  218.55 13.95 270 top
C8208  1500PF/50V  [VX_C0402_SMALL]  222.36 17.38 0 top
C8209  22UF/6.3V  [VX_C0603_H39_SMALL]  204.7 11.67 270 top
C8210  22UF/6.3V  [VX_C0603_H39_SMALL]  207.24 11.67 270 top
C8211  22UF/6.3V  [VX_C0603_H39_SMALL]  205.97 11.67 270 top
C8212  22UF/6.3V  [VX_C0603_H39_SMALL]  202.16 11.67 270 top
C8213  22UF/6.3V  [VX_C0603_H39_SMALL]  203.43 11.67 270 top
C8214  10PF/50V  [VX_C0402_SMALL]  228.2 12.81 0 top
C8215  2.2NF/50V  [VX_C0402_SMALL]  227.18 14.97 90 top
C8216  220PF/50V  [VX_C0402_SMALL]  212.32 10.9 0 top
C8300  10UF/6.3V  [VX_C0603_SMALL]  24.29 51.92 270 top
C8301  10UF/6.3V  [VX_C0603_SMALL]  23.02 51.92 270 top
C8302  0.1UF/10V  [VX_C0402_SMALL]  25.43 53.32 90 top
C8303  0.033UF/16V  [VX_C0402_SMALL]  24.74 47.92 270 top
C8304  1500PF/50V  [VX_C0402_SMALL]  19.54 67.93 270 top
C8305  0.1UF/25V  [VX_C0402_SMALL]  20.43 67.93 270 top
C8306  10UF/25V  [VX_C0805_H57_SMALL]  21.7 67.29 270 top
C8307  10UF/25V  [VX_C0805_H57_SMALL]  23.48 67.29 270 top
C8308  10UF/6.3V  [VX_C0603_SMALL]  26.95 53.58 180 top
C8309  0.1UF/25V  [VX_C0603_SMALL]  31.14 53.58 270 top
C8310  0.1UF/25V  [VX_C0402_SMALL]  30.21 46.34 0 top
C8311  22UF/6.3V  [VX_C0603_H39_SMALL]  35.39 100.34 180 top
C8312  22UF/6.3V  [VX_C0603_H39_SMALL]  35.39 101.61 180 top
C8313  22UF/6.3V  [VX_C0603_H39_SMALL]  35.39 102.88 180 top
C8314  1500PF/50V  [VX_C0402_SMALL]  27.54 68.05 0 top
C8315  22UF/6.3V  [VX_C0603_H39_SMALL]  35.39 99.07 180 top
C8316  22UF/6.3V  [VX_C0603_H39_SMALL]  35.39 97.8 180 top
C8317  22UF/6.3V  [VX_C0603_H39_SMALL]  35.39 96.53 180 top
C8318  0.1UF/10V  [VX_C0402_SMALL]  32.29 49.13 90 top
C8319  0.01UF/16V  [VX_C0402_SMALL]  27.33 45.96 270 top
C8320  0.01UF/50V  [VX_C0402_SMALL]  24.44 45.96 90 top
C8321  0.01UF/50V  [VX_C0402_SMALL]  24.87 44.69 0 top
C8322  1500PF/50V  [VX_C0402_SMALL]  28.22 45.96 270 top
C8323  10PF/50V  [VX_C0402_SMALL]  19.36 75.11 180 top
C8324  2.2NF/50V  [VX_C0402_SMALL]  19.36 75.94 180 top
C8325  10PF/50V  [VX_C0402_SMALL]  42.78 114.54 90 top
C8326  2.2NF/50V  [VX_C0402_SMALL]  41.89 114.54 90 top
C8327  10PF/50V  [VX_C0402_SMALL]  21.97 51.98 270 top
C8328  2.2NF/50V  [VX_C0402_SMALL]  21.09 51.98 270 top
C8400  1000PF/50V  [VX_C0402_SMALL]  219.87 25.71 90 top
C8401  10UF/6.3V  [VX_C0603_SMALL]  215.25 28.3 180 top
C8402  0.1UF/10V  [VX_C0402_SMALL]  221.6 30.08 0 top
C8404  10UF/6.3V  [VX_C0603_SMALL]  224.52 29.57 90 top
C8601  1500PF/50V  [VX_C0402_SMALL]  123.65 56.62 0 top
C8602  0.1UF/10V  [VX_C0402_SMALL]  118.73 61.07 180 top
C8603  22UF/6.3V  [VX_C0805_H57_SMALL]  127.82 74.4 0 top
C8604  0.22UF/25V  [VX_C0603_SMALL]  116.61 64.86 270 top
C8605  220PF/50V  [VX_C0402_SMALL]  123.55 58.02 90 bottom
C8606  22UF/6.3V  [VX_C0805_H57_SMALL]  127.82 72.63 0 top
C8607  0.1UF/16V  [VX_C0402_SMALL]  121.82 57.16 90 bottom
C8608  22UF/6.3V  [VX_C0805_H57_SMALL]  122.04 72.87 180 top
C8609  22UF/6.3V  [VX_C0805_H57_SMALL]  122.03 74.66 180 top
C8610  1500PF/50V  [VX_C0603_SMALL]  126.17 59.93 270 bottom
C8611  0.1UF/10V  [VX_C0402_SMALL]  125.84 61.2 0 top
C8612  10UF/25V  [VX_C0805_H57_SMALL]  123.45 53.51 0 top
C8613  10UF/25V  [VX_C0805_H57_SMALL]  123.45 55.29 0 top
C8614  10PF/50V  [VX_C0402_SMALL]  123.95 85.07 180 top
C8615  2.2NF/50V  [VX_C0402_SMALL]  123.95 84.23 180 top
C8616  22UF/6.3V  [VX_C0805_H57_SMALL]  122.03 76.44 180 top
C8701  4700PF/50V  [VX_C0402_SMALL]  131.93 164.7 90 top
C8702  1500PF/50V  [VX_C0402_SMALL]  129.27 162.34 90 bottom
C8703  0.01UF/25V  [VX_C0402_SMALL]  130.16 164.7 90 top
C8704  0.01UF/25V  [VX_C0402_SMALL]  128.38 164.7 90 top
C8705  0.068UF/10V  [VX_C0402_SMALL]  121.39 153.14 90 top
C8706  0.068UF/10V  [VX_C0402_SMALL]  117.84 153.98 0 top
C8707  0.068UF/10V  [VX_C0402_SMALL]  117.84 156.67 0 top
C8708  0.068UF/10V  [VX_C0402_SMALL]  117.84 159.21 0 top
C8709  0.068UF/10V  [VX_C0402_SMALL]  117.84 160.97 0 top
C8710  0.068UF/10V  [VX_C0402_SMALL]  117.58 162.59 270 top
C8711  0.068UF/10V  [VX_C0402_SMALL]  118.5 162.59 270 top
C8712  0.068UF/10V  [VX_C0402_SMALL]  119.39 162.59 270 top
C8713  0.33UF/10V  [VX_C0402_SMALL]  122.28 153.14 270 top
C8714  1000PF/50V  [VX_C0402_SMALL]  123.68 152.51 180 top
C8715  820PF/50V  [VX_C0402_SMALL]  123.68 154.03 180 top
C8716  1000PF/50V  [VX_C0402_SMALL]  125.84 153.14 270 bottom
C8717  2200PF/50V  [VX_C0402_SMALL]  130.32 153.83 270 top
C8718  47PF/50V  [VX_C0402_SMALL]  129.43 153.83 270 top
C8719  330PF/50V  [VX_C0402_SMALL]  128.67 152 270 top
C8720  1000PF/50V  [VX_C0402_SMALL]  131.22 156.06 90 top
C8721  1UF/10V  [VX_C0603_SMALL]  129.77 155.81 0 bottom
C8722  2.2UF/6.3V  [VX_C0603_SMALL]  186.04 164.19 270 top
C8723  0.22UF/25V  [VX_C0603_SMALL]  180.7 163.05 90 top
C8724  10UF/25V  [VX_C0805_H57_SMALL]  166.86 188.58 90 top
C8725  10UF/25V  [VX_C0805_H57_SMALL]  130.54 181.95 90 top
C8726  1500PF/50V  [VX_C0603_SMALL]  184.77 180.45 180 bottom
C8727  2.2UF/6.3V  [VX_C0603_SMALL]  146.54 164.95 270 top
C8728  0.22UF/25V  [VX_C0603_SMALL]  141.33 163.81 90 top
C8729  10UF/25V  [VX_C0805_H57_SMALL]  134.08 181.95 90 top
C8730  10UF/25V  [VX_C0805_H57_SMALL]  135.86 181.95 90 top
C8731  1500PF/50V  [VX_C0603_SMALL]  147.43 178.16 90 bottom
C8732  2.2UF/6.3V  [VX_C0603_SMALL]  160.94 164.95 270 top
C8733  0.22UF/25V  [VX_C0603_SMALL]  155.68 163.81 90 top
C8734  10UF/25V  [VX_C0805_H57_SMALL]  146.16 189.47 90 top
C8735  10UF/25V  [VX_C0805_H57_SMALL]  156.83 189.72 90 top
C8736  1500PF/50V  [VX_C0603_SMALL]  148.7 178.16 90 bottom
C8737  2.2UF/6.3V  [VX_C0603_SMALL]  173.97 164.95 270 top
C8738  0.22UF/25V  [VX_C0603_SMALL]  168.64 163.81 90 top
C8739  10UF/25V  [VX_C0805_H57_SMALL]  180.32 188.58 90 top
C8740  10UF/25V  [VX_C0805_H57_SMALL]  168.64 188.58 90 top
C8741  1500PF/50V  [VX_C0603_SMALL]  161.78 178.16 90 bottom
C8752  22UF/6.3V  [VX_C0805_H57_SMALL]  135.54 114.99 0 top
C8753  22UF/6.3V  [VX_C0805_H57_SMALL]  141.38 120.64 270 top
C8754  22UF/6.3V  [VX_C0805_H57_SMALL]  135.42 145.88 180 bottom
C8755  22UF/6.3V  [VX_C0805_H57_SMALL]  180.27 146.88 180 bottom
C8756  22UF/6.3V  [VX_C0805_H57_SMALL]  142.6 145.45 0 top
C8757  22UF/6.3V  [VX_C0805_H57_SMALL]  180.17 146.95 180 top
C8758  22UF/6.3V  [VX_C0805_H57_SMALL]  180.27 148.71 180 bottom
C8759  22UF/6.3V  [VX_C0805_H57_SMALL]  135.42 147.79 180 bottom
C8760  22UF/6.3V  [VX_C0805_H57_SMALL]  180.27 145.06 180 bottom
C8761  22UF/6.3V  [VX_C0805_H57_SMALL]  135.13 145.42 180 top
C8762  22UF/6.3V  [VX_C0805_H57_SMALL]  137.91 143.84 270 bottom
C8763  22UF/6.3V  [VX_C0805_H57_SMALL]  143.62 144.63 0 bottom
C8764  22UF/6.3V  [VX_C0805_H57_SMALL]  181.21 154.77 90 top
C8765  22UF/6.3V  [VX_C0805_H57_SMALL]  170.03 144.76 0 bottom
C8766  22UF/6.3V  [VX_C0805_H57_SMALL]  180.17 152.41 180 top
C8767  22UF/6.3V  [VX_C0805_H57_SMALL]  156.7 144.76 180 bottom
C8768  0.1UF/25V  [VX_C0603_SMALL]  126.09 157.72 180 bottom
C8769  10UF/25V  [VX_C0805_H57_SMALL]  174.61 188.58 90 top
C8770  10UF/25V  [VX_C0805_H57_SMALL]  178.54 188.58 90 top
C8771  10UF/25V  [VX_C0805_H57_SMALL]  155.05 189.72 90 top
C8772  10UF/25V  [VX_C0805_H57_SMALL]  144.38 189.47 90 top
C8773  10UF/25V  [VX_C0805_H57_SMALL]  161.27 188.58 90 top
C8774  10UF/25V  [VX_C0805_H57_SMALL]  163.05 188.58 90 top
C8775  10UF/25V  [VX_C0805_H57_SMALL]  132.31 181.95 90 top
C8776  10UF/25V  [VX_C0805_H57_SMALL]  172.83 188.58 90 top
C8781  22UF/6.3V  [VX_C0805_H57_SMALL]  139.63 120.65 270 top
C8782  22UF/6.3V  [VX_C0805_H57_SMALL]  137.89 120.66 270 top
C8783  22UF/6.3V  [VX_C0805_H57_SMALL]  180.17 150.5 180 top
C8784  22UF/6.3V  [VX_C0805_H57_SMALL]  180.27 150.53 180 bottom
C8785  22UF/6.3V  [VX_C0805_H57_SMALL]  180.17 148.72 180 top
C8786  22UF/6.3V  [VX_C0805_H57_SMALL]  135.54 120.39 0 top
C8787  22UF/6.3V  [VX_C0805_H57_SMALL]  135.54 118.59 0 top
C8788  22UF/6.3V  [VX_C0805_H57_SMALL]  135.54 116.79 0 top
C8800  470PF/50V  [VX_C0402_SMALL]  9.15 82.43 0 top
C8801  0.01UF/50V  [VX_C0402_SMALL]  10.83 80.86 270 top
C8802  1500PF/50V  [VX_C0402_SMALL]  299.57 14.61 180 top
C8803  10UF/25V  [VX_C0805_H57_SMALL]  289.01 15.02 270 top
C8804  1500PF/50V  [VX_C0402_SMALL]  290.38 15.27 90 top
C8806  2.2UF/25V  [VX_C1206_H49]  10.9 71.74 90 top
C8807  0.1UF/25V  [VX_C0402_SMALL]  279.3 38.34 0 top
C8808  0.1UF/25V  [VX_C0402_SMALL]  278.54 37.07 90 top
C8809  0.1UF/25V  [VX_C0402_SMALL]  279.94 37.07 90 top
C8810  1500PF/50V  [VX_C0402_SMALL]  281.16 18.65 180 top
C8811  10UF/25V  [VX_C0805_H57_SMALL]  281.16 16.36 180 top
C8812  10UF/25V  [VX_C0805_H57_SMALL]  281.16 14.59 180 top
C8813  0.1UF/25V  [VX_C0402_SMALL]  281.16 17.76 180 top
C8814  0.1UF/10V  [VX_C0402_SMALL]  269.5 35.29 90 top
C8815  100PF/50V  [VX_C0402_SMALL]  146.03 16.49 270 bottom
C8816  0.47UF/25V  [VX_C0603_SMALL]  281.16 35.08 180 top
C8817  0.047UF/16V  [VX_C0402_SMALL]  281.29 33.13 0 top
C8818  10UF/25V  [VX_C0805_H57_SMALL]  301.35 15.48 270 top
C8819  10UF/25V  [VX_C0805_H57_SMALL]  303.13 15.48 270 top
C8820  10UF/25V  [VX_C0805_H57_SMALL]  304.91 15.48 270 top
C8821  1UF/25V  [VX_C0603_SMALL]  280.78 30.08 270 top
C8822  0.1UF/25V  [VX_C0402_SMALL]  281.16 19.67 180 top
C8823  0.1UF/25V  [VX_C0402_SMALL]  286.49 28 270 top
C8824  0.01UF/50V  [VX_C0402_SMALL]  277.86 28.86 90 top
C8825  0.1UF/25V  [VX_C0402_SMALL]  284.59 28.64 180 top
C8826  0.1UF/25V  [VX_C0402_SMALL]  284.59 27.24 180 top
C8827  0.022UF/16V  [VX_C0402_SMALL]  270.87 38.21 180 top
C8839  100PF/50V  [VX_C0402_SMALL]  145.14 15.98 270 bottom
C8900  0.1UF/25V  [VX_C0402_SMALL]  230.51 96.3 90 top
C8901  10UF/25V  [VX_C0805_H57_SMALL]  227.44 96.63 90 top
C8902  10UF/25V  [VX_C0805_H57_SMALL]  229.22 96.63 90 top
C8903  0.22UF/16V  [VX_C0402_SMALL]  245.34 81.26 90 top
C8904  0.01UF/16V  [VX_C0402_SMALL]  254.34 81.29 90 bottom
C8906  1500PF/50V  [VX_C0402_SMALL]  219.82 98.28 180 top
C8907  100PF/50V  [VX_C0402_SMALL]  251.24 85.81 180 top
C8908  0.1UF/10V  [VX_C0402_SMALL]  252.46 82.66 0 bottom
C8909  2700PF/50V  [VX_C0402_SMALL]  252.33 82.02 0 top
C8910  2.2UF/6.3V  [VX_C0603_SMALL]  244.46 82.02 0 bottom
C8912  390PF/50V  [VX_C0402_SMALL]  249.94 86.72 90 top
C8915  0.22UF/25V  [VX_C0603_SMALL]  251.87 89.19 0 top
C8916  10PF/50V  [VX_C0402_SMALL]  211.56 97.97 0 top
C8925  10UF/25V  [VX_C0805_H57_SMALL]  236.28 93.28 90 top
C8926  0.1UF/25V  [VX_C0402_SMALL]  237.67 93.28 90 top
C8927  1500PF/50V  [VX_C0402_SMALL]  242.8 91.42 0 bottom
C8928  10UF/25V  [VX_C0805_H57_SMALL]  234.47 93.28 90 top
C8929  0.22UF/16V  [VX_C0402_SMALL]  245.47 85.2 270 top
C09100  1UF/6.3V  [VX_C0201_H14]  86.25 115.17 0 top
C9100  0.01UF/16V  [VX_C0402_SMALL]  197.31 35.52 270 top
C09101  1UF/6.3V  [VX_C0201_H14]  81.3 121.95 0 top
C9101  4.7UF/10V  [VX_C0402_H26_SMALL]  193.86 34.73 0 top
C09102  1UF/6.3V  [VX_C0201_H14]  90.31 122.71 0 top
C9103  0.047UF/16V  [VX_C0402_SMALL]  197.8 38.08 0 top
C09103  1UF/6.3V  [VX_C0201_H14]  86 125.76 180 top
C09104  1UF/6.3V  [VX_C0201_H14]  87.14 123.48 180 top
C09105  1UF/6.3V  [VX_C0201_H14]  85.62 122.71 0 top
C9105  0.1UF/10V  [VX_C0402_SMALL]  197.8 37.17 0 top
C9106  0.01UF/16V  [VX_C0402_SMALL]  132.52 75.11 270 top
C09106  1UF/6.3V  [VX_C0201_H14]  90.31 121.95 0 top
C09107  1UF/6.3V  [VX_C0201_H14]  88.41 125.76 0 top
C9107  4.7UF/10V  [VX_C0402_H26_SMALL]  195.76 39.71 180 top
C9108  1000PF/50V  [VX_C0402_SMALL]  191.9 37.72 180 top
C09108  1UF/6.3V  [VX_C0201_H14]  90.72 125.76 180 top
C09109  1UF/6.3V  [VX_C0201_H14]  90.31 123.48 0 top
C9109  1000PF/50V  [VX_C0402_SMALL]  191.9 36.15 180 top
C09110  1UF/6.3V  [VX_C0201_H14]  91.08 115.14 0 top
C9110  0.1UF/10V  [VX_C0402_SMALL]  194.16 39.71 0 top
C09111  1UF/6.3V  [VX_C0201_H14]  91.08 114.38 0 top
C9111  0.068UF/16V  [VX_C0402_SMALL]  243.69 19.54 0 top
C09112  1UF/6.3V  [VX_C0201_H14]  93.62 114.46 0 top
C9112  0.1UF/10V  [VX_C0402_SMALL]  240.14 16.11 0 top
C09113  1UF/6.3V  [VX_C0201_H14]  91.84 121.95 180 top
C9113  0.1UF/10V  [VX_C0402_SMALL]  239.63 20.94 0 top
C9114  0.1UF/10V  [VX_C0402_SMALL]  243.69 18.65 0 top
C09114  1UF/6.3V  [VX_C0201_H14]  86.25 112.88 0 top
C9115  1UF/10V  [VX_C0402_SMALL]  241.92 20.94 180 top
C09115  1UF/6.3V  [VX_C0201_H14]  83.46 113.57 180 top
C9116  1000PF/50V  [VX_C0402_SMALL]  238.11 19.29 180 top
C09116  1UF/6.3V  [VX_C0201_H14]  81.3 127.67 180 top
C09117  1UF/6.3V  [VX_C0201_H14]  86 127.67 180 top
C9117  1000PF/50V  [VX_C0402_SMALL]  238.11 18.02 180 top
C9118  0.033UF/16V  [VX_C0402_SMALL]  260.33 77.86 270 top
C09118  1UF/6.3V  [VX_C0201_H14]  93.11 127.67 0 top
C9119  0.1UF/10V  [VX_C0402_SMALL]  257.28 81.77 270 top
C09119  1UF/6.3V  [VX_C0201_H14]  81.3 120.43 0 top
C09120  1UF/6.3V  [VX_C0201_H14]  82.82 121.19 180 top
C9120  0.033UF/16V  [VX_C0402_SMALL]  259.01 80.3 180 bottom
C9121  1UF/10V  [VX_C0402_SMALL]  261.98 79.36 90 top
C09121  1UF/6.3V  [VX_C0201_H14]  90.31 121.19 0 top
C09122  1UF/6.3V  [VX_C0201_H14]  81.3 123.48 0 top
C9122  1UF/10V  [VX_C0402_SMALL]  258.3 78.19 270 top
C09123  1UF/6.3V  [VX_C0201_H14]  87.14 121.19 180 top
C9123  1000PF/50V  [VX_C0402_SMALL]  259.95 84.06 90 top
C9124  1000PF/50V  [VX_C0402_SMALL]  259.06 84.06 90 top
C09124  1UF/6.3V  [VX_C0201_H14]  86.25 113.65 0 top
C09125  1UF/6.3V  [VX_C0201_H14]  89.04 113.7 180 top
C9125  0.1UF/10V  [VX_C0402_SMALL]  260.84 84.06 90 top
C09126  1UF/6.3V  [VX_C0201_H14]  89.04 112.97 180 top
C09127  1UF/6.3V  [VX_C0201_H14]  85.62 121.19 0 top
C09128  1UF/6.3V  [VX_C0201_H14]  81.3 122.71 0 top
C09129  1UF/6.3V  [VX_C0201_H14]  90.72 127.67 180 top
C09130  1UF/6.3V  [VX_C0201_H14]  85.62 121.95 0 top
C9133  0.1UF/10V  [VX_C0402_SMALL]  238.36 23.48 180 top
C9134  0.01UF/16V  [VX_C0402_SMALL]  238.36 24.37 180 top
C9135  0.1UF/10V  [VX_C0402_SMALL]  135.87 92.21 180 top
C9136  0.1UF/10V  [VX_C0402_SMALL]  193.86 33.84 0 top
C9200  2.2UF/6.3V  [VX_C0402_SMALL]  176.38 37.45 180 top
C9400  1500PF/50V  [VX_C0402_SMALL]  100.56 168 90 bottom
C9401  10UF/25V  [VX_C0805_H57_SMALL]  97.39 168 90 bottom
C9402  10UF/25V  [VX_C0805_H57_SMALL]  99.17 168 90 bottom
C9403  1UF/16V  [VX_C0402_SMALL]  102.34 171.56 90 bottom
C9405  0.22UF/25V  [VX_C0603_SMALL]  107.3 165.21 180 bottom
C9406  22UF/6.3V  [VX_C0603_H39_SMALL]  117.07 162.03 0 bottom
C9407  22UF/6.3V  [VX_C0603_H39_SMALL]  106.55 159.24 180 bottom
C9408  22UF/6.3V  [VX_C0603_H39_SMALL]  106.55 160.51 180 bottom
C9409  22UF/6.3V  [VX_C0603_H39_SMALL]  117.07 160.51 0 bottom
C9410  22UF/6.3V  [VX_C0603_H39_SMALL]  117.07 163.56 0 bottom
C9411  0.01UF/16V  [VX_C0402_SMALL]  101.2 164.19 180 bottom
C9412  1500PF/50V  [VX_C0402_SMALL]  104.98 171.58 90 bottom
C9414  1UF/6.3V  [VX_C0402_SMALL]  106.79 156.88 180 bottom
C9415  2.2NF/50V  [VX_C0402_SMALL]  106.79 156 180 bottom
C9416  220PF/50V  [VX_C0402_SMALL]  107.42 162.8 180 bottom
C9500  1500PF/50V  [VX_C0402_SMALL]  87.61 5.57 270 top
C9501  10UF/25V  [VX_C0805_H57_SMALL]  86.21 5.57 270 top
C9502  10UF/25V  [VX_C0805_H57_SMALL]  84.44 5.57 270 top
C9503  0.1UF/10V  [VX_C0402_SMALL]  91.27 2.85 180 top
C9504  0.1UF/10V  [VX_C0402_SMALL]  91.04 9.25 90 top
C9505  0.22UF/25V  [VX_C0603_SMALL]  93.33 7.22 90 top
C9506  22UF/6.3V  [VX_C0603_H39_SMALL]  106.15 8.11 270 top
C9507  22UF/6.3V  [VX_C0603_H39_SMALL]  107.8 8.11 270 top
C9508  22UF/6.3V  [VX_C0603_H39_SMALL]  104.25 12.3 90 top
C9509  22UF/6.3V  [VX_C0603_H39_SMALL]  106.03 12.3 90 top
C9510  22UF/6.3V  [VX_C0603_H39_SMALL]  107.8 12.3 90 top
C9511  0.1UF/10V  [VX_C0402_SMALL]  97.8 13.57 90 bottom
C9512  1500PF/50V  [VX_C0402_SMALL]  93.4 2.52 180 top
C9513  220PF/50V  [VX_C0402_SMALL]  92.82 11.41 270 top
C9514  10PF/50V  [VX_C0402_SMALL]  115.93 12.94 0 top
C9515  2.2NF/50V  [VX_C0402_SMALL]  115.93 12.05 0 top
C9600  22UF/6.3V  [VX_C0603_H39_SMALL]  116.95 134.09 180 bottom
C9601  220PF/50V  [VX_C0402_SMALL]  113.52 150.35 0 bottom
C9602  22UF/6.3V  [VX_C0603_H39_SMALL]  116.95 135.49 180 bottom
C9603  0.1UF/25V  [VX_C0402_SMALL]  114.03 143.87 0 bottom
C9604  10UF/25V  [VX_C0805_H57_SMALL]  118.34 152.18 0 bottom
C9605  10UF/25V  [VX_C0805_H57_SMALL]  118.34 153.96 0 bottom
C9606  10PF/50V  [VX_C0402_SMALL]  127.36 125.08 270 bottom
C9607  2.2NF/50V  [VX_C0402_SMALL]  116.95 136.63 180 bottom
C9608  0.1UF/10V  [VX_C0402_SMALL]  121.6 147.25 0 bottom
C9609  0.22UF/25V  [VX_C0603_SMALL]  116.95 145.14 180 bottom
C9610  0.1UF/25V  [VX_C0402_SMALL]  118.09 150.86 0 bottom
C9611  1500PF/50V  [VX_C0402_SMALL]  120.53 148.11 90 top
C9612  0.1UF/10V  [VX_C0402_SMALL]  114.66 147.3 180 bottom
C9613  22UF/6.3V  [VX_C0603_H39_SMALL]  119.74 132.32 180 bottom
C9614  22UF/6.3V  [VX_C0603_H39_SMALL]  119.87 130.79 180 bottom
C9701  0.22UF/25V  [VX_C0603_SMALL]  202.14 184.4 180 top
C9702  10UF/25V  [VX_C0805_H57_SMALL]  191.5 177.65 180 top
C9703  2700PF/50V  [VX_C0402_SMALL]  200.77 189.24 180 bottom
C9704  0.22UF/25V  [VX_C0603_SMALL]  196.58 184.89 0 top
C9705  0.1UF/6.3V  [VX_C0402_SMALL]  189.08 152.53 180 bottom
C9706  0.1UF/6.3V  [VX_C0402_SMALL]  200.79 146.46 0 bottom
C9707  10UF/6.3V  [VX_C0603_SMALL]  93.07 177.15 180 top
C9708  10UF/6.3V  [VX_C0603_SMALL]  89.64 178.92 270 top
C9709  2.2UF/6.3V  [VX_C0603_SMALL]  200.77 185.53 90 bottom
C9710  10UF/25V  [VX_C0805_H57_SMALL]  206.48 177.91 0 top
C9711  390PF/50V  [VX_C0402_SMALL]  196.32 189.34 180 top
C9712  1500PF/50V  [VX_C0603_SMALL]  210.34 173.46 90 bottom
C9713  0.47UF/10V  [VX_C0402_SMALL]  206.28 187.51 0 top
C9714  0.1UF/25V  [VX_C0603_SMALL]  206.61 181.34 0 top
C9716  10UF/6.3V  [VX_C0603_SMALL]  97.26 181.72 90 top
C9717  10UF/25V  [VX_C0805_H57_SMALL]  206.48 179.81 0 top
C9718  10UF/25V  [VX_C0805_H57_SMALL]  206.48 176.13 0 top
C9719  0.1UF/6.3V  [VX_C0402_SMALL]  96.12 181.72 90 top
C9720  4700PF/50V  [VX_C0402_SMALL]  206.23 190.1 180 top
C9721  0.1UF/16V  [VX_C0402_SMALL]  200.64 190.61 0 top
C9722  10UF/25V  [VX_C0805_H57_SMALL]  191.5 175.88 180 top
C9723  100PF/50V  [VX_C0402_SMALL]  196.42 190.61 270 top
C9724  10UF/25V  [VX_C0805_H57_SMALL]  191.5 179.43 180 top
C9725  1500PF/50V  [VX_C0603_SMALL]  185.53 170.67 90 bottom
C9726  10UF/6.3V  [VX_C0603_SMALL]  97.24 179.05 270 top
C18100  1UF/6.3V  [VX_C0402_SMALL]  116.36 44.08 0 top
C18101  10UF/6.3V  [VX_C0402_H28_SMALL]  116.36 43.21 0 top
C18102  1UF/6.3V  [VX_C0402_SMALL]  116.36 41.84 0 top
C18103  10UF/6.3V  [VX_C0402_H28_SMALL]  116.36 40.98 0 top
C18104  1UF/6.3V  [VX_C0402_SMALL]  116.36 40.14 0 top
C18105  10UF/6.3V  [VX_C0402_H28_SMALL]  114.41 55.02 0 bottom
C18106  1UF/6.3V  [VX_C0402_SMALL]  114.38 64.73 0 bottom
